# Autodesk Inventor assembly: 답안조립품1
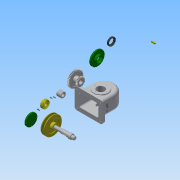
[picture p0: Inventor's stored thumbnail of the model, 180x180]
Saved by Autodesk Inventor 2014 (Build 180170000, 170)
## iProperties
Created: 2016-10
Part Number: 답안조립품1
Document SubType Name: Assembly
Designer: net
Author: net
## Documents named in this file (15)
- C:\Users\net\Desktop\461007V1012\답안조립품1.iam
- C:\Users\net\Desktop\461007V1012\본체.ipt
- C:\Users\net\Desktop\461007V1012\V-벨트풀리.ipt
- C:\Users\net\Desktop\461007V1012\뒤커버.ipt
- C:\Users\net\Desktop\461007V1012\멈춤나사 - M4x10.ipt
- C:\Users\net\Desktop\461007V1012\베어링 6203.ipt
- C:\Users\net\Desktop\461007V1012\볼트 M3 x 8.ipt
- C:\Users\net\Desktop\461007V1012\볼트 M3 x 10.ipt
- C:\Users\net\Desktop\461007V1012\부시.ipt
- C:\Users\net\Desktop\461007V1012\스퍼기어.ipt
- C:\Users\net\Desktop\461007V1012\앞커버.ipt
- C:\Users\net\Desktop\461007V1012\오일씰 28 40 8.ipt
- C:\Users\net\Desktop\461007V1012\축.ipt
- C:\Users\net\Desktop\461007V1012\키 - 5 x 5 x 18.ipt
- C:\Users\net\Desktop\461007V1012\키 - 6 x 6 x 22.ipt
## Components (3 placed, 3 different names)
1. V-벨트풀리:1
2. ISO 4762 M3 x 8:1
3. ISO 4762 M3 x 10:1
